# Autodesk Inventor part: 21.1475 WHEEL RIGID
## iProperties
Created: 2007-04
Part Number: 21.1475 WHEEL RIGID
Document SubType Name: Modeling
Designer: Andy Moles
Material: Steel
Mass: 205.079 g
Surface Area: 153.436 cm^2
Volume: 26.1247 cm^3
Density: 7.85 g/cm^3
Author: Andy Moles
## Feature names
1. Base1
